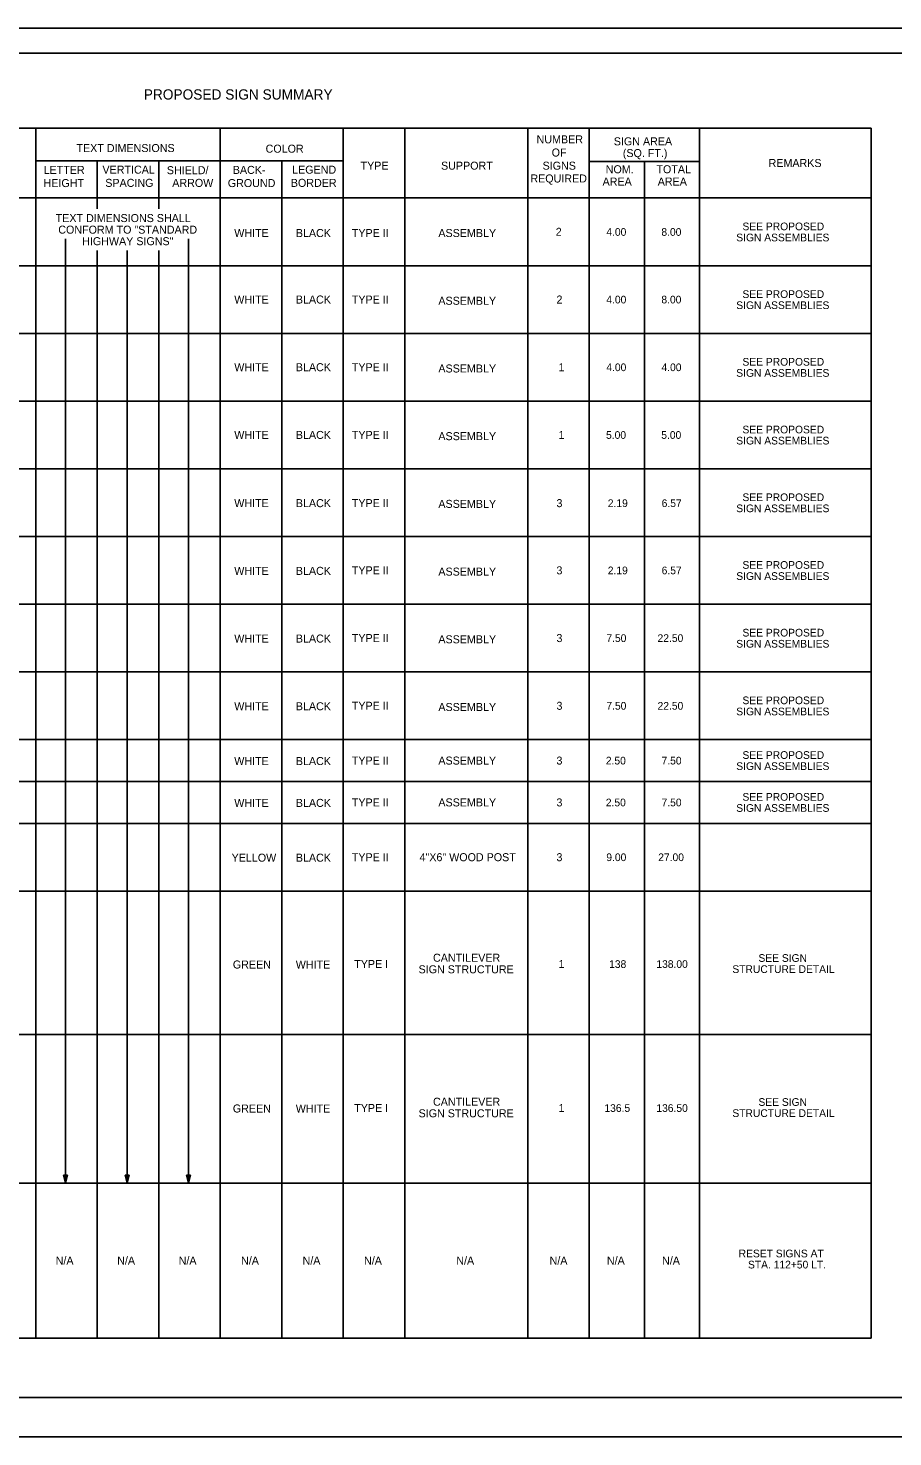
# Model space of a CAD drawing. Extents: x 29767 to 1670682, y 5748 to 339066.
# Drawn here: x 1670046 to 1670383, y 338516 to 339066 of the extents above; entities that cross this region are included whole.
import ezdxf

# ---------------------------------------------------------------- set-up
doc = ezdxf.new("R2010")
doc.units = 0
for name, color, linetype in [('D_Roadway_Pavement', 7, 'Continuous'), ('S_Curb_Type_1', 7, 'Continuous'), ('S_Curb_Type_5', 7, 'Continuous'), ('TEXT', 7, 'Continuous')]:
    doc.layers.add(name, color=color, linetype=linetype)

msp = doc.modelspace()

# ---------------------------------------------------------------- linework, layer by layer
at = {"layer": 'D_Roadway_Pavement'}
msp.add_lwpolyline([(1669832.5, 338515.81), (1670682.5, 338515.81), (1670682.5, 339065.81), (1669832.5, 339065.81)], close=True, dxfattribs=at)
at = {"layer": 'S_Curb_Type_1'}
for p, q in [((1670374.95, 339026.77), (1669890.74, 339026.77)), ((1670048.98, 338554.38), (1670048.98, 339026.77)), ((1670120.98, 338554.38), (1670120.98, 339026.77)), ((1670168.98, 338554.38), (1670168.98, 339026.77)), ((1670192.98, 338554.38), (1670192.98, 339026.77)), ((1670240.98, 338554.38), (1670240.98, 339026.77)), ((1670264.98, 338554.38), (1670264.98, 339026.77)), ((1670308.05, 338554.38), (1670308.05, 339026.77)), ((1670374.95, 338554.38), (1670374.95, 339026.77)), ((1670048.98, 339013.95), (1670120.98, 339013.95)), ((1670072.98, 338998.7), (1670072.98, 339013.95)), ((1670072.98, 338995.28), (1670072.98, 339013.95)), ((1670096.98, 338995.28), (1670096.98, 339013.95)), ((1670120.98, 339013.95), (1670144.98, 339013.95)), ((1670144.98, 338554.38), (1670144.98, 339013.95)), ((1670144.98, 339013.95), (1670168.98, 339013.95)), ((1670264.98, 339013.81), (1670308.05, 339013.81)), ((1670286.51, 338554.38), (1670286.51, 339013.81)), ((1670374.95, 338999.52), (1669890.74, 338999.52)), ((1670072.98, 338554.38), (1670072.98, 338978.94)), ((1670096.98, 338554.38), (1670096.98, 338978.94)), ((1670374.95, 338973.08), (1669890.74, 338973.08)), ((1670374.95, 338946.65), (1669890.74, 338946.65)), ((1670374.95, 338920.21), (1669890.74, 338920.21)), ((1670374.95, 338893.77), (1669890.74, 338893.77)), ((1670374.95, 338867.34), (1669890.74, 338867.34)), ((1670374.95, 338840.9), (1669890.74, 338840.9)), ((1670374.95, 338814.46), (1669890.74, 338814.46)), ((1670374.95, 338788.03), (1669890.74, 338788.03)), ((1670374.95, 338771.68), (1669890.74, 338771.68)), ((1670374.95, 338755.34), (1669890.74, 338755.34)), ((1670374.95, 338728.9), (1669890.74, 338728.9)), ((1670374.95, 338672.87), (1669890.74, 338672.87)), ((1670374.95, 338614.86), (1669890.74, 338614.86)), ((1670374.95, 338554.38), (1669890.74, 338554.38))]:
    msp.add_line(p, q, dxfattribs=at)
at = {"layer": 'S_Curb_Type_5'}
for p, q in [((1670060.64, 338614.86), (1670060.64, 338983.57)), ((1670108.64, 338614.86), (1670108.64, 338983.57)), ((1670084.64, 338614.86), (1670084.64, 338978.94)), ((1670060.64, 338614.86), (1670059.86, 338617.99)), ((1670059.86, 338617.99), (1670060.64, 338614.86)), ((1670060.64, 338617.99), (1670059.86, 338617.99)), ((1670061.42, 338617.99), (1670060.64, 338614.86)), ((1670060.64, 338614.86), (1670061.42, 338617.99)), ((1670061.42, 338617.99), (1670060.64, 338617.99)), ((1670060.64, 338617.99), (1670060.64, 338614.86)), ((1670060.64, 338614.86), (1670060.64, 338617.99)), ((1670084.64, 338614.86), (1670083.86, 338617.99)), ((1670083.86, 338617.99), (1670084.64, 338614.86)), ((1670084.64, 338617.99), (1670083.86, 338617.99)), ((1670085.42, 338617.99), (1670084.64, 338614.86)), ((1670084.64, 338614.86), (1670084.64, 338617.99)), ((1670084.64, 338614.86), (1670085.42, 338617.99)), ((1670085.42, 338617.99), (1670084.64, 338617.99)), ((1670084.64, 338617.99), (1670084.64, 338614.86)), ((1670108.64, 338614.86), (1670107.86, 338617.99)), ((1670107.86, 338617.99), (1670108.64, 338614.86)), ((1670108.64, 338617.99), (1670107.86, 338617.99)), ((1670109.42, 338617.99), (1670108.64, 338614.86)), ((1670108.64, 338614.86), (1670108.64, 338617.99)), ((1670108.64, 338614.86), (1670109.42, 338617.99)), ((1670109.42, 338617.99), (1670108.64, 338617.99)), ((1670108.64, 338617.99), (1670108.64, 338614.86)), ((1670059.86, 338614.86), (1670061.42, 338614.86)), ((1670083.86, 338614.86), (1670085.42, 338614.86)), ((1670107.86, 338614.86), (1670109.42, 338614.86))]:
    msp.add_line(p, q, dxfattribs=at)
at = {"layer": 'TEXT'}
for p, q in [((1670672.96, 339056.11), (1669872.96, 339056.11)), ((1669872.96, 338531.11), (1670672.96, 338531.11))]:
    msp.add_line(p, q, dxfattribs=at)

# ---------------------------------------------------------------- texts
at = {"layer": 'S_Curb_Type_5'}
for s, height, p in [('PROPOSED SIGN SUMMARY', 4, (1670091.12, 339037.94)), ('TEXT DIMENSIONS', 3.125, (1670064.86, 339017.44)), ('COLOR', 3.125, (1670138.67, 339017.2)), ('NUMBER', 3.125, (1670244.43, 339020.84)), ('SIGN AREA', 3.125, (1670274.56, 339020.06)), ('OF', 3.125, (1670250.32, 339015.7)), ('(SQ. FT.)', 3.125, (1670278.08, 339015.49)), ('REMARKS', 3.125, (1670334.97, 339011.6)), ('LETTER', 3.125, (1670052.04, 339008.91)), ('VERTICAL', 3.125, (1670075, 339009)), ('SHIELD/', 3.125, (1670100.13, 339008.8)), ('BACK-', 3.125, (1670125.86, 339008.91)), ('LEGEND', 3.125, (1670149.02, 339009)), ('TYPE', 3.125, (1670175.74, 339010.56)), ('SUPPORT', 3.125, (1670207.14, 339010.56)), ('REQUIRED', 3.125, (1670242.01, 339005.56)), ('SIGNS', 3.125, (1670246.77, 339010.56)), ('NOM.', 3.125, (1670271.41, 339009.16)), ('TOTAL', 3.125, (1670291.2, 339009.16)), ('HEIGHT', 3.125, (1670052.02, 339003.77)), ('SPACING', 3.125, (1670076.1, 339003.85)), ('ARROW', 3.125, (1670102.24, 339003.84)), ('GROUND', 3.125, (1670123.92, 339003.77)), ('BORDER', 3.125, (1670148.51, 339003.85)), ('AREA', 3.125, (1670270.17, 339004.37)), ('AREA', 3.125, (1670291.71, 339004.37)), ('TEXT DIMENSIONS SHALL', 3.125, (1670056.75, 338990.1)), ('CONFORM TO "STANDARD', 3.125, (1670057.76, 338985.58)), ('WHITE', 3.125, (1670126.44, 338984.26)), ('BLACK', 3.125, (1670150.47, 338984.26)), ('TYPE II', 3.125, (1670172.33, 338984.26)), ('ASSEMBLY', 3.125, (1670206.1, 338984.26)), ('2', 3.12, (1670251.9, 338984.74)), ('4.00', 3, (1670271.64, 338984.74)), ('8.00', 3, (1670293.13, 338984.74)), ('SEE PROPOSED ', 3, (1670324.77, 338986.91)), ('HIGHWAY SIGNS"', 3.125, (1670067.09, 338981.07)), ('SIGN ASSEMBLIES', 3, (1670322.35, 338982.58)), ('WHITE', 3.125, (1670126.44, 338958.3)), ('BLACK', 3.125, (1670150.47, 338958.3)), ('TYPE II', 3.125, (1670172.33, 338958.3)), ('ASSEMBLY', 3.125, (1670206.1, 338957.82)), ('2', 3.12, (1670252.2, 338958.3)), ('4.00', 3, (1670271.64, 338958.34)), ('8.00', 3, (1670293.13, 338958.34)), ('SIGN ASSEMBLIES', 3, (1670322.35, 338956.14)), ('SEE PROPOSED ', 3, (1670324.77, 338960.47)), ('SEE PROPOSED ', 3, (1670324.77, 338934.04)), ('WHITE', 3.125, (1670126.44, 338931.87)), ('BLACK', 3.125, (1670150.47, 338931.87)), ('TYPE II', 3.125, (1670172.33, 338931.87)), ('ASSEMBLY', 3.125, (1670206.1, 338931.38)), ('1', 3.12, (1670252.98, 338931.87)), ('4.00', 3, (1670271.64, 338931.9)), ('4.00', 3, (1670293.17, 338931.9)), ('SIGN ASSEMBLIES', 3, (1670322.35, 338929.7)), ('SEE PROPOSED ', 3, (1670324.77, 338907.6)), ('WHITE', 3.125, (1670126.44, 338905.43)), ('BLACK', 3.125, (1670150.47, 338905.43)), ('TYPE II', 3.125, (1670172.33, 338905.43)), ('ASSEMBLY', 3.125, (1670206.1, 338904.95)), ('1', 3.12, (1670252.98, 338905.43)), ('5.00', 3, (1670271.54, 338905.47)), ('5.00', 3, (1670293.08, 338905.47)), ('SIGN ASSEMBLIES', 3, (1670322.35, 338903.27)), ('WHITE', 3.125, (1670126.44, 338878.8)), ('BLACK', 3.125, (1670150.47, 338878.8)), ('TYPE II', 3.125, (1670172.33, 338878.8)), ('3', 3.12, (1670252.18, 338878.8)), ('2.19', 3, (1670272.21, 338878.84)), ('6.57', 3, (1670293.24, 338878.84)), ('SEE PROPOSED ', 3, (1670324.77, 338881.16)), ('ASSEMBLY', 3.125, (1670206.1, 338878.51)), ('SIGN ASSEMBLIES', 3, (1670322.35, 338876.83)), ('WHITE', 3.125, (1670126.44, 338852.36)), ('BLACK', 3.125, (1670150.47, 338852.36)), ('TYPE II', 3.125, (1670172.33, 338852.56)), ('ASSEMBLY', 3.125, (1670206.1, 338852.07)), ('3', 3.12, (1670252.18, 338852.56)), ('2.19', 3, (1670272.21, 338852.59)), ('6.57', 3, (1670293.24, 338852.59)), ('SEE PROPOSED ', 3, (1670324.77, 338854.73)), ('SIGN ASSEMBLIES', 3, (1670322.35, 338850.39)), ('WHITE', 3.125, (1670126.44, 338825.93)), ('BLACK', 3.125, (1670150.47, 338825.93)), ('TYPE II', 3.125, (1670172.33, 338826.12)), ('ASSEMBLY', 3.125, (1670206.1, 338825.64)), ('3', 3.12, (1670252.18, 338826.12)), ('7.50', 3, (1670271.66, 338826.16)), ('22.50', 3, (1670291.64, 338826.16)), ('SIGN ASSEMBLIES', 3, (1670322.35, 338823.96)), ('SEE PROPOSED ', 3, (1670324.77, 338828.29)), ('SEE PROPOSED ', 3, (1670324.77, 338801.86)), ('WHITE', 3.125, (1670126.44, 338799.49)), ('BLACK', 3.125, (1670150.47, 338799.49)), ('TYPE II', 3.125, (1670172.33, 338799.68)), ('ASSEMBLY', 3.125, (1670206.1, 338799.2)), ('3', 3.12, (1670252.18, 338799.68)), ('7.50', 3, (1670271.66, 338799.72)), ('22.50', 3, (1670291.64, 338799.72)), ('SIGN ASSEMBLIES', 3, (1670322.35, 338797.52)), ('SEE PROPOSED ', 3, (1670324.77, 338780.51)), ('WHITE', 3.125, (1670126.44, 338778.1)), ('BLACK', 3.125, (1670150.47, 338778.1)), ('TYPE II', 3.125, (1670172.33, 338778.29)), ('ASSEMBLY', 3.125, (1670206.1, 338778.29)), ('3', 3.12, (1670252.18, 338778.29)), ('2.50', 3, (1670271.45, 338778.33)), ('7.50', 3, (1670293.2, 338778.33)), ('SIGN ASSEMBLIES', 3, (1670322.35, 338776.18)), ('SEE PROPOSED ', 3, (1670324.77, 338764.17)), ('WHITE', 3.125, (1670126.44, 338761.76)), ('BLACK', 3.125, (1670150.47, 338761.76)), ('TYPE II', 3.125, (1670172.33, 338761.95)), ('ASSEMBLY', 3.125, (1670206.1, 338761.95)), ('3', 3.12, (1670252.18, 338761.95)), ('2.50', 3, (1670271.45, 338761.99)), ('7.50', 3, (1670293.2, 338761.99)), ('SIGN ASSEMBLIES', 3, (1670322.35, 338759.84)), ('YELLOW', 3.125, (1670125.4, 338740.37)), ('BLACK', 3.125, (1670150.47, 338740.37)), ('TYPE II', 3.125, (1670172.33, 338740.56)), ('4"X6" WOOD POST', 3.125, (1670198.75, 338740.56)), ('3', 3.12, (1670252.18, 338740.56)), ('9.00', 3, (1670271.64, 338740.6)), ('27.00', 3, (1670291.9, 338740.6)), ('GREEN', 3.125, (1670125.89, 338698.66)), ('WHITE', 3.125, (1670150.44, 338698.66)), ('TYPE I', 3.125, (1670173.26, 338698.86)), ('CANTILEVER', 3.125, (1670204, 338701.31)), ('1', 3.12, (1670252.98, 338698.86)), ('138', 3, (1670272.74, 338698.89)), ('138.00', 3, (1670291.17, 338698.89)), ('SEE SIGN ', 3, (1670331.01, 338701.26)), ('SIGN STRUCTURE', 3.125, (1670198.37, 338696.79)), ('STRUCTURE DETAIL', 3, (1670320.83, 338696.92)), ('GREEN', 3.125, (1670125.89, 338642.44)), ('WHITE', 3.125, (1670150.44, 338642.44)), ('TYPE I', 3.125, (1670173.26, 338642.63)), ('CANTILEVER', 3.125, (1670204, 338645.09)), ('1', 3.12, (1670252.98, 338642.63)), ('136.5', 3, (1670270.9, 338642.67)), ('136.50', 3, (1670291.17, 338642.67)), ('SEE SIGN ', 3, (1670331.01, 338645.03)), ('SIGN STRUCTURE', 3.125, (1670198.37, 338640.57)), ('STRUCTURE DETAIL', 3, (1670320.83, 338640.7)), ('N/A', 3.125, (1670056.75, 338583.06)), ('N/A', 3.125, (1670080.75, 338583.06)), ('N/A', 3.125, (1670104.75, 338583.06)), ('N/A', 3.125, (1670129.09, 338583.06)), ('N/A', 3.125, (1670153.09, 338583.06)), ('N/A', 3.125, (1670177.09, 338583.06)), ('N/A', 3.125, (1670213.09, 338583.06)), ('N/A', 3.125, (1670249.5, 338583.06)), ('N/A', 3.125, (1670271.86, 338583.06)), ('N/A', 3.125, (1670293.39, 338583.06)), ('RESET SIGNS AT ', 3, (1670323.28, 338585.89)), ('STA. 112+50 LT.', 3, (1670326.93, 338581.55))]:
    msp.add_text(s, height=height, dxfattribs=at).set_placement(p)

doc.saveas('drawing.dxf')
